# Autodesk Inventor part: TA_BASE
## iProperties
Created: 2006-11
Part Number: TA_BASE
Document SubType Name: Modeling
Designer: Lab User
Author: Lab User
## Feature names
1. Extrusion1
2. Hole1
3. Extrusion2
4. Hole2
5. Hole3
6. Hole4
7. Hole5
8. Hole6
9. Hole7
10. Hole8
11. Extrusion3
12. Hole9
13. Hole10
14. Extrusion4
15. Fillet1
